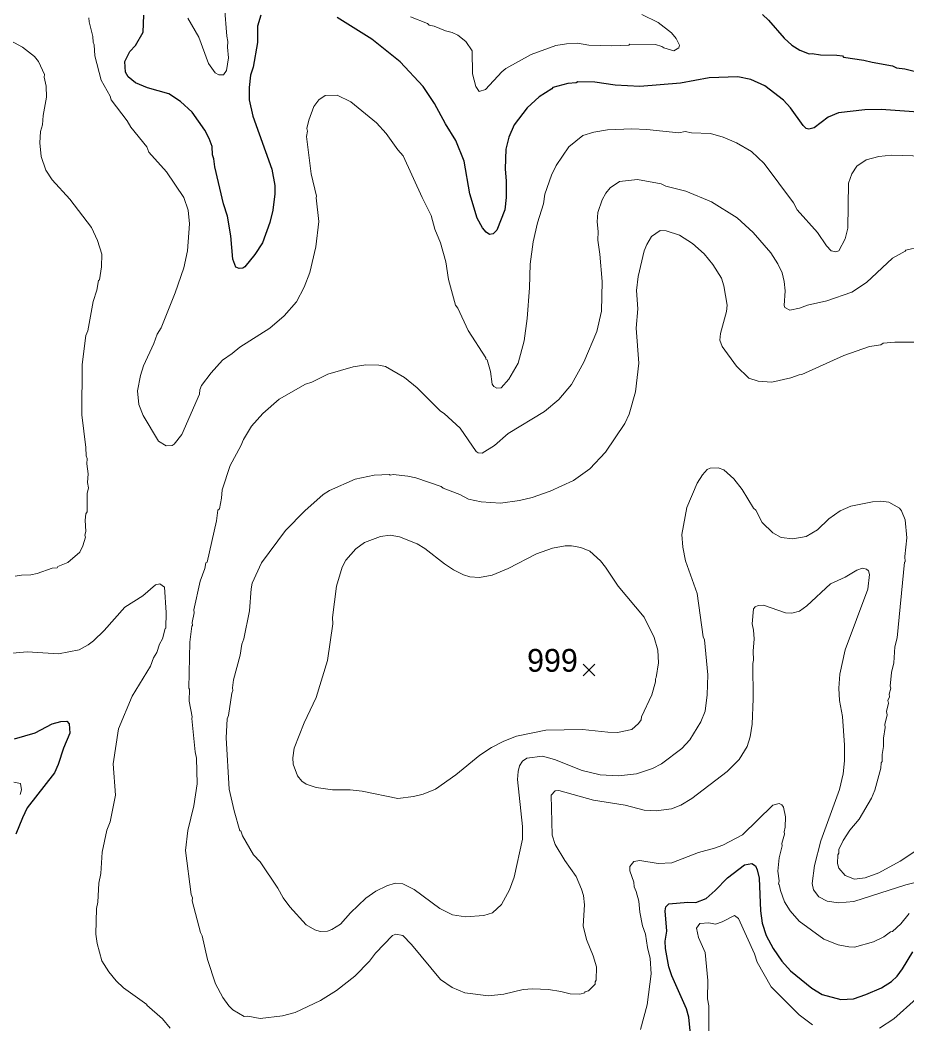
# Model space of a CAD drawing. Extents: x 265.7 to 292.1, y 7676.2 to 7704.2.
# Drawn here: x 279.917 to 283.035, y 7688.918 to 7692.446 of the extents above; entities that cross this region are included whole.
import ezdxf
from ezdxf.enums import TextEntityAlignment as Align

# ---------------------------------------------------------------- set-up
doc = ezdxf.new("R2010")
doc.units = 0
doc.header["$LTSCALE"] = 0.032
for name, color, linetype, lineweight in [('1', 7, 'Continuous', 25), ('2', 7, 'Continuous', 13), ('21', 7, 'Continuous', 25)]:
    doc.layers.add(name, color=color, linetype=linetype, lineweight=lineweight)
doc.layers.add('61', color=7, linetype='Continuous')

msp = doc.modelspace()

# ---------------------------------------------------------------- linework, layer by layer
at = {"layer": '1'}
for points in [[(280.8051, 7691.778), (280.7948, 7691.7349), (280.7692, 7691.6631), (280.7429, 7691.6224), (280.707, 7691.5793), (280.6998, 7691.5745), (280.6878, 7691.5729), (280.6751, 7691.5777), (280.6647, 7691.6057), (280.6575, 7691.6871), (280.6463, 7691.7573), (280.6328, 7691.8004), (280.6016, 7691.9296), (280.5985, 7691.9584), (280.5937, 7691.9727), (280.5921, 7692.0015), (280.5817, 7692.0302), (280.5665, 7692.0589), (280.5226, 7692.122), (280.4812, 7692.1594), (280.4397, 7692.1866), (280.3655, 7692.2081), (280.3224, 7692.2257), (280.2976, 7692.2464), (280.288, 7692.2624), (280.2857, 7692.2999), (280.3032, 7692.335), (280.3224, 7692.3565), (280.3495, 7692.4036), (280.3519, 7692.4627)], [(280.7636, 7692.4635), (280.7517, 7692.4244), (280.7517, 7692.3669), (280.7365, 7692.2807), (280.7277, 7692.252), (280.7221, 7692.2089)], [(283.1567, 7692.1164), (282.9445, 7692.1315), (282.887, 7692.1307), (282.7945, 7692.1203), (282.7577, 7692.1052), (282.7091, 7692.0677), (282.6899, 7692.0621), (282.6811, 7692.0645), (282.67, 7692.0749), (282.6253, 7692.1371), (282.6005, 7692.1642), (282.5351, 7692.2145), (282.4864, 7692.2368), (282.4402, 7692.2464), (282.3396, 7692.2424), (282.2391, 7692.2241), (282.0954, 7692.2121), (282.0093, 7692.2177), (281.9374, 7692.2273), (281.8784, 7692.2289), (281.872, 7692.2257), (281.8433, 7692.2233), (281.7898, 7692.2089), (281.7866, 7692.2041), (281.7419, 7692.1762), (281.7004, 7692.1371), (281.6542, 7692.0781), (281.6358, 7692.035), (281.6246, 7691.9919), (281.6222, 7691.9233), (281.6262, 7691.8802), (281.6262, 7691.8227), (281.6214, 7691.7796), (281.5927, 7691.7078), (281.5799, 7691.6942), (281.5672, 7691.6926), (281.556, 7691.7006), (281.5432, 7691.7158), (281.5241, 7691.7493), (281.4978, 7691.8355), (281.4778, 7691.9504), (281.4491, 7692.0222), (281.4124, 7692.0813), (281.3741, 7692.1531), (281.3342, 7692.2129), (281.2536, 7692.2991), (281.1538, 7692.3789), (281.0317, 7692.4555)], [(282.5271, 7692.4651), (282.5479, 7692.4459), (282.6029, 7692.3821), (282.6309, 7692.3573), (282.6588, 7692.3398), (282.6915, 7692.327), (282.7019, 7692.3286), (282.7306, 7692.3238), (282.7881, 7692.323), (282.808, 7692.3198), (282.812, 7692.3158), (282.8838, 7692.3055), (282.9126, 7692.2975), (282.9844, 7692.2847), (282.9987, 7692.2783), (283.0275, 7692.2751)], [(283.0275, 7692.2751), (283.0562, 7692.2672), (283.1424, 7692.26), (283.1942, 7692.2632), (283.1942, 7692.2656), (283.2142, 7692.272), (283.2405, 7692.2879)], [(280.7221, 7692.2089), (280.7229, 7692.1658), (280.7349, 7692.1084), (280.8027, 7691.9217), (280.8123, 7691.8642), (280.8123, 7691.8355), (280.8051, 7691.778)], [(279.8979, 7689.9196), (279.9697, 7689.9411), (280.0303, 7689.9722), (280.0606, 7689.981), (280.0814, 7689.9818), (280.0894, 7689.973), (280.0925, 7689.9403), (280.0702, 7689.8869), (280.051, 7689.8294), (280.0375, 7689.8007), (279.9425, 7689.677), (279.925, 7689.6427), (279.9026, 7689.5852)], [(282.2758, 7688.8703), (282.2678, 7688.9421), (282.2606, 7688.9708), (282.2079, 7689.0873), (282.1984, 7689.1192), (282.1856, 7689.1831), (282.1848, 7689.2094), (282.1904, 7689.2437), (282.1848, 7689.3155), (282.1872, 7689.3299), (282.1984, 7689.3402), (282.2646, 7689.3458), (282.2933, 7689.345), (282.3292, 7689.3594), (282.3604, 7689.3865), (282.4042, 7689.432), (282.4641, 7689.4767)], [(282.4641, 7689.4767), (282.4896, 7689.4823), (282.5024, 7689.4735), (282.5088, 7689.4592), (282.5152, 7689.4304), (282.5199, 7689.3155), (282.5263, 7689.2724)], [(282.5263, 7689.2724), (282.5399, 7689.2293), (282.5646, 7689.1831), (282.5957, 7689.1392), (282.6261, 7689.1049), (282.7011, 7689.0434), (282.737, 7689.0219), (282.8024, 7689.0043), (282.8471, 7689.0067), (282.8902, 7689.0211), (282.9453, 7689.045), (282.9812, 7689.0673), (283.0003, 7689.0857), (283.0195, 7689.1112), (283.0562, 7689.1719)]]:
    msp.add_lwpolyline(points, dxfattribs=at)
at = {"layer": '2'}
for points in [[(280.636, 7692.493), (280.6439, 7692.3893), (280.6479, 7692.3701), (280.6463, 7692.351), (280.6495, 7692.3127), (280.6423, 7692.2688), (280.6328, 7692.2536), (280.616, 7692.2536), (280.6025, 7692.2608), (280.5793, 7692.2935), (280.5458, 7692.3861), (280.5067, 7692.4531)], [(280.1596, 7692.4403), (280.1588, 7692.4539)], [(280.2338, 7692.1786), (280.2019, 7692.2345), (280.1803, 7692.3206), (280.1779, 7692.3589), (280.1739, 7692.3685), (280.1731, 7692.3877), (280.1596, 7692.4403)], [(282.1034, 7692.4659), (282.1609, 7692.4379), (282.2071, 7692.4012), (282.2231, 7692.3813), (282.2359, 7692.3581), (282.2335, 7692.3478), (282.2159, 7692.3382), (282.18, 7692.3478), (282.1728, 7692.3534), (282.1513, 7692.3597), (282.0603, 7692.3613), (282.0571, 7692.3581), (281.9965, 7692.3557), (281.9167, 7692.3581), (281.8768, 7692.3645), (281.8385, 7692.3629), (281.8002, 7692.3565), (281.714, 7692.3246), (281.6246, 7692.2752), (281.6103, 7692.264), (281.5536, 7692.2025), (281.5305, 7692.1954), (281.5193, 7692.2129), (281.5073, 7692.2568), (281.5065, 7692.3374), (281.4842, 7692.3701), (281.4563, 7692.3925), (281.4363, 7692.402), (281.4124, 7692.4076), (281.3725, 7692.4244), (281.3557, 7692.4284), (281.3493, 7692.434), (281.2895, 7692.4571)], [(279.8843, 7692.3725), (279.925, 7692.351), (279.9681, 7692.3174), (279.9816, 7692.3007), (280.0024, 7692.2544), (280.0016, 7692.2456), (280.0088, 7692.2137), (280.0096, 7692.1754), (279.9984, 7692.11), (279.996, 7692.0781), (279.9888, 7692.0541), (279.9864, 7692.0142), (279.9912, 7691.9664), (280.008, 7691.9185), (280.0303, 7691.885), (280.0918, 7691.8171), (280.1684, 7691.7174), (280.1891, 7691.6711), (280.2043, 7691.6232), (280.2035, 7691.5785), (280.1963, 7691.5331), (280.1923, 7691.5307), (280.1867, 7691.4972), (280.1739, 7691.4573), (280.1556, 7691.3535), (280.1484, 7691.3376), (280.1348, 7691.2354), (280.134, 7691.0583), (280.1484, 7690.9434), (280.1492, 7690.9146), (280.1524, 7690.9051), (280.1516, 7690.8859), (280.1564, 7690.8508), (280.1542, 7690.8205)], [(282.3444, 7692.0469), (282.2774, 7692.0493), (282.255, 7692.0541), (282.2327, 7692.0493), (282.121, 7692.0613), (282.0683, 7692.0637), (281.9821, 7692.0605), (281.9343, 7692.0525), (281.896, 7692.0398), (281.8465, 7691.9999), (281.8018, 7691.9344), (281.7858, 7691.9009), (281.7619, 7691.8339), (281.7571, 7691.8004), (281.7364, 7691.7333), (281.7204, 7691.6663), (281.71, 7691.5881), (281.7084, 7691.5051), (281.7004, 7691.3966), (281.6893, 7691.3184), (281.6685, 7691.2402), (281.6358, 7691.1843), (281.6079, 7691.1532), (281.5927, 7691.1524), (281.5823, 7691.158), (281.5768, 7691.166), (281.5712, 7691.2115), (281.5592, 7691.2522), (281.5544, 7691.2538), (281.5544, 7691.2586), (281.4922, 7691.3551), (281.4555, 7691.4333), (281.4475, 7691.4445), (281.4235, 7691.5339), (281.414, 7691.5961), (281.3956, 7691.6631), (281.3757, 7691.711), (281.3629, 7691.7589), (281.3302, 7691.8227), (281.264, 7691.9687), (281.2448, 7691.9895), (281.2041, 7692.0477), (281.1698, 7692.0845), (281.0804, 7692.1587), (281.0318, 7692.1818), (280.9895, 7692.181), (280.9679, 7692.1658), (280.9496, 7692.1419), (280.932, 7692.094), (280.9256, 7692.0653), (280.9272, 7692.0557), (280.924, 7692.0366), (280.9408, 7691.9057), (280.9591, 7691.8275), (280.9575, 7691.8211), (280.9671, 7691.7381), (280.9567, 7691.6488), (280.936, 7691.5594), (280.916, 7691.5067), (280.8889, 7691.4557), (280.845, 7691.4062), (280.7948, 7691.3631), (280.6894, 7691.2961), (280.6631, 7691.2745), (280.6288, 7691.2506), (280.5889, 7691.2059), (280.5554, 7691.162), (280.549, 7691.146), (280.5474, 7691.1309), (280.4859, 7690.9896), (280.4588, 7690.9553), (280.4516, 7690.9513), (280.4301, 7690.9497), (280.4038, 7690.9657), (280.3495, 7691.0567), (280.3351, 7691.095), (280.3303, 7691.1429), (280.3399, 7691.1971), (280.3511, 7691.2306), (280.387, 7691.3088), (280.399, 7691.3423), (280.4133, 7691.3647), (280.4628, 7691.4876), (280.4923, 7691.5754), (280.5059, 7691.6344), (280.5131, 7691.7302), (280.5075, 7691.778), (280.4931, 7691.8227), (280.4317, 7691.9121), (280.3702, 7691.9815), (280.3631, 7691.9999), (280.3064, 7692.0701), (280.2936, 7692.0924), (280.237, 7692.1658), (280.2338, 7692.1786)], [(282.6492, 7691.7788), (282.6365, 7691.8036), (282.5335, 7691.9416), (282.4888, 7691.9839), (282.4362, 7692.015), (282.3891, 7692.035), (282.3444, 7692.0469)], [(283.0929, 7691.9671), (282.9812, 7691.9711), (282.9365, 7691.9663), (282.8918, 7691.9544), (282.8591, 7691.932), (282.8415, 7691.9057), (282.8296, 7691.8722), (282.8272, 7691.7142), (282.8184, 7691.6767), (282.796, 7691.6352), (282.7849, 7691.6312), (282.7689, 7691.6344), (282.7522, 7691.652), (282.721, 7691.6998), (282.6492, 7691.7788)], [(283.0817, 7691.6488), (283.0314, 7691.6376), (283.0283, 7691.6336), (282.9844, 7691.6097), (282.8934, 7691.5235), (282.8415, 7691.4892), (282.753, 7691.4596), (282.6859, 7691.4437), (282.6572, 7691.4333), (282.6229, 7691.4269), (282.6061, 7691.4357), (282.6029, 7691.4429), (282.6069, 7691.494), (282.6037, 7691.5275), (282.5958, 7691.5578), (282.5814, 7691.5897), (282.5567, 7691.628), (282.4944, 7691.699), (282.4378, 7691.7509), (282.3476, 7691.8068), (282.2582, 7691.8451), (282.1872, 7691.8626), (282.1704, 7691.8706), (282.0875, 7691.8858), (282.0244, 7691.8786), (281.9917, 7691.8562), (281.9765, 7691.8379), (281.963, 7691.8147), (281.9478, 7691.7701), (281.9454, 7691.7365), (281.9494, 7691.703), (281.9486, 7691.6727), (281.9558, 7691.6232), (281.9638, 7691.5275), (281.9614, 7691.4229)], [(283.1041, 7691.3136), (282.9923, 7691.3136), (282.9516, 7691.3104), (282.9429, 7691.3048), (282.903, 7691.2992), (282.8136, 7691.2673), (282.6652, 7691.2003), (282.6556, 7691.1995), (282.6269, 7691.1883), (282.5599, 7691.1732), (282.512, 7691.1772), (282.4793, 7691.1875), (282.4362, 7691.2298), (282.3851, 7691.2993), (282.3771, 7691.3216), (282.3795, 7691.3439), (282.4003, 7691.4221), (282.4027, 7691.4445), (282.3907, 7691.5115), (282.3827, 7691.5394), (282.3524, 7691.5865), (282.3221, 7691.6248), (282.2806, 7691.6607), (282.2351, 7691.6895), (282.188, 7691.7054), (282.168, 7691.7062), (282.1369, 7691.6855), (282.1202, 7691.6567), (282.1114, 7691.6344), (282.0906, 7691.545), (282.0843, 7691.4956), (282.089, 7691.4317), (282.0827, 7691.3631), (282.093, 7691.2402), (282.0803, 7691.1397), (282.0587, 7691.0615), (282.0436, 7691.0279), (281.9749, 7690.9274), (281.9199, 7690.8684), (281.8624, 7690.8277), (281.7802, 7690.7901), (281.7172, 7690.7678), (281.6725, 7690.7574), (281.6055, 7690.7487), (281.5385, 7690.7526), (281.4938, 7690.7622), (281.4627, 7690.7782), (281.4044, 7690.8013), (281.3972, 7690.8069), (281.3087, 7690.8372), (281.2799, 7690.8436), (281.2289, 7690.8484), (281.2177, 7690.8468), (281.2161, 7690.8492), (281.1618, 7690.8468), (281.0948, 7690.8324), (281.0054, 7690.7933), (280.9831, 7690.779), (280.9176, 7690.7207), (280.8498, 7690.6521), (280.766, 7690.5388), (280.7333, 7690.467), (280.7293, 7690.447), (280.7237, 7690.3704), (280.7038, 7690.2715), (280.6966, 7690.2523), (280.691, 7690.214), (280.6679, 7690.1278), (280.6639, 7690.0991), (280.6655, 7690.0895), (280.6615, 7690.08), (280.6495, 7690.0018), (280.6447, 7689.9906), (280.6416, 7689.9236), (280.6527, 7689.7432), (280.6695, 7689.6666), (280.6894, 7689.5972), (280.6926, 7689.5972), (280.699, 7689.5789)], [(281.9614, 7691.4229), (281.9446, 7691.3519), (281.8991, 7691.2434), (281.856, 7691.1652), (281.8106, 7691.1125), (281.7603, 7691.0702), (281.6334, 7690.9928)], [(281.6334, 7690.9928), (281.5855, 7690.9505), (281.5417, 7690.9242), (281.5273, 7690.925), (281.5209, 7690.9298), (281.4642, 7691.012), (281.4084, 7691.0631), (281.3956, 7691.071), (281.3126, 7691.154), (281.2687, 7691.1899), (281.2017, 7691.2282), (281.1778, 7691.233), (281.1331, 7691.2338), (281.0884, 7691.2274), (280.999, 7691.2019), (280.9432, 7691.1732), (280.9208, 7691.1668), (280.8283, 7691.1133), (280.7708, 7691.0631), (280.7309, 7691.0184), (280.7022, 7690.9721), (280.6934, 7690.9497), (280.6559, 7690.8811), (280.628, 7690.7949), (280.6256, 7690.7662), (280.6176, 7690.7279), (280.6128, 7690.7231), (280.6072, 7690.6864), (280.5745, 7690.5412), (280.5697, 7690.538), (280.5665, 7690.5188), (280.5498, 7690.4742), (280.5282, 7690.3736), (280.529, 7690.3624), (280.5219, 7690.3289), (280.5227, 7690.3178), (280.5203, 7690.3154), (280.5139, 7690.2603), (280.5099, 7690.0983), (280.5131, 7690.0943), (280.5115, 7690.0528), (280.5219, 7689.997), (280.5203, 7689.9914), (280.5322, 7689.8741), (280.537, 7689.8518), (280.5394, 7689.7624), (280.5274, 7689.6842), (280.5067, 7689.598), (280.4987, 7689.5278), (280.5187, 7689.373), (280.5227, 7689.3618), (280.5219, 7689.3506), (280.5514, 7689.2389), (280.557, 7689.2277), (280.5761, 7689.1448), (280.604, 7689.0586), (280.6304, 7689.0107), (280.6511, 7688.9812), (280.6647, 7688.9676), (280.7054, 7688.9445), (280.7173, 7688.9453), (280.7612, 7688.9373), (280.8394, 7688.9461), (280.8841, 7688.9588), (280.9735, 7689.0003), (281.0294, 7689.0354), (281.094, 7689.0857), (281.1459, 7689.1384), (281.1666, 7689.1671), (281.2265, 7689.2285), (281.2384, 7689.2341), (281.2624, 7689.2293), (281.2927, 7689.1974), (281.3948, 7689.0745), (281.4363, 7689.0458), (281.481, 7689.0275), (281.564, 7689.0171), (281.6183, 7689.0227), (281.6853, 7689.0386), (281.7188, 7689.0418), (281.7747, 7689.0386), (281.8178, 7689.0322), (281.8513, 7689.0235), (281.8848, 7689.0227), (281.9023, 7689.0275), (281.9031, 7689.0306), (281.9159, 7689.0346), (281.939, 7689.0578), (281.939, 7689.0658), (281.943, 7689.0721), (281.9438, 7689.1192), (281.9319, 7689.1575), (281.9079, 7689.215), (281.8967, 7689.2629), (281.9015, 7689.3363)], [(280.9224, 7689.266), (280.9528, 7689.2485), (280.9719, 7689.2429), (280.9974, 7689.2437), (281.0134, 7689.2501), (281.0437, 7689.2692), (281.0788, 7689.3083), (281.1331, 7689.3602), (281.1682, 7689.3849), (281.2065, 7689.4033), (281.2352, 7689.4129), (281.2624, 7689.4105), (281.3023, 7689.3905), (281.3932, 7689.3235), (281.4379, 7689.3012), (281.4826, 7689.2948), (281.548, 7689.2996), (281.5776, 7689.3083), (281.6095, 7689.3379), (281.6374, 7689.3889), (281.6542, 7689.4336), (281.6829, 7689.5677), (281.6837, 7689.6124), (281.6661, 7689.7767), (281.6677, 7689.8055), (281.6725, 7689.8246), (281.6829, 7689.8414), (281.6981, 7689.8517), (281.7539, 7689.8589), (281.7954, 7689.8478), (281.8928, 7689.8087), (281.9566, 7689.7935), (282.0204, 7689.7895), (282.0843, 7689.7975), (282.1401, 7689.8158), (282.172, 7689.8318), (282.2439, 7689.8861), (282.2718, 7689.9164), (282.3109, 7689.9794), (282.3252, 7690.0177), (282.3332, 7690.0752), (282.3348, 7690.1454), (282.3229, 7690.2683), (282.3189, 7690.2779), (282.2981, 7690.4311), (282.2566, 7690.546), (282.247, 7690.5939), (282.2439, 7690.6385), (282.2614, 7690.7327), (282.2981, 7690.8189), (282.3157, 7690.8476), (282.3332, 7690.866), (282.3428, 7690.8707), (282.3715, 7690.8723), (282.3907, 7690.8652), (282.4266, 7690.8332), (282.4553, 7690.7965), (282.4952, 7690.7311), (282.5032, 7690.7231), (282.5255, 7690.6808), (282.563, 7690.6441), (282.5934, 7690.6274), (282.6333, 7690.6226), (282.6811, 7690.6306), (282.721, 7690.6545), (282.7601, 7690.6936), (282.8008, 7690.7215), (282.8375, 7690.7375), (282.9141, 7690.7526), (282.9429, 7690.755), (282.9716, 7690.7519), (283.0083, 7690.7311), (283.0163, 7690.7215), (283.029, 7690.6896), (283.0346, 7690.6258), (283.0275, 7690.5603), (283.0283, 7690.542), (283.0259, 7690.5404), (283.0003, 7690.2747), (282.9923, 7690.2428), (282.9891, 7690.1869), (282.9812, 7690.1534), (282.9764, 7690.1055), (282.978, 7690.0975), (282.9724, 7690.0768), (282.974, 7690.068), (282.9684, 7690.0544), (282.97, 7690.0449), (282.9636, 7690.0161), (282.9652, 7690.0042), (282.9572, 7689.9699), (282.9588, 7689.9603), (282.9532, 7689.922), (282.9532, 7689.8932), (282.9477, 7689.8645)], [(280.1542, 7690.8205), (280.158, 7690.8021), (280.1532, 7690.7822), (280.1532, 7690.7175), (280.1484, 7690.7104), (280.146, 7690.688), (280.1484, 7690.6489), (280.1452, 7690.6353), (280.1468, 7690.6282), (280.138, 7690.5986), (280.1269, 7690.5763), (280.0854, 7690.5396), (280.0503, 7690.5252), (280.0479, 7690.5212), (280.0303, 7690.5196), (279.9777, 7690.5013), (279.9553, 7690.4965), (279.9218, 7690.4957), (279.8995, 7690.4917)], [(281.7874, 7689.582), (281.7842, 7689.7225), (281.7986, 7689.7368), (281.8114, 7689.7384), (281.9327, 7689.7049), (282.0444, 7689.6866), (282.1114, 7689.669), (282.1529, 7689.6666), (282.2072, 7689.6738), (282.2399, 7689.6874), (282.279, 7689.7105), (282.4035, 7689.8055), (282.4449, 7689.8478), (282.4737, 7689.8932), (282.484, 7689.9268), (282.4912, 7689.9714), (282.4944, 7690.0608), (282.4928, 7690.1853), (282.496, 7690.1965), (282.4944, 7690.2284), (282.4976, 7690.2715), (282.496, 7690.3018), (282.4912, 7690.3241), (282.4952, 7690.3768), (282.5016, 7690.384), (282.512, 7690.3888), (282.5311, 7690.3896), (282.6077, 7690.3632), (282.6301, 7690.3616), (282.6572, 7690.3688), (282.6827, 7690.3872), (282.7657, 7690.4646), (282.8184, 7690.4885), (282.8583, 7690.5125), (282.879, 7690.5196), (282.8934, 7690.5164), (282.8998, 7690.5101), (282.9038, 7690.4981), (282.8974, 7690.4462), (282.8176, 7690.2332), (282.7992, 7690.147), (282.796, 7690.0975), (282.7984, 7690.0544), (282.808, 7689.9986), (282.816, 7689.898), (282.8152, 7689.8422), (282.8104, 7689.7975), (282.7976, 7689.7416), (282.7322, 7689.5613), (282.7099, 7689.4751), (282.7019, 7689.4113), (282.7067, 7689.3897), (282.7258, 7689.365), (282.7546, 7689.349), (282.7945, 7689.3442), (282.8479, 7689.3482), (283.0307, 7689.4073), (283.1551, 7689.4376)], [(279.826, 7690.2156), (279.9425, 7690.2252), (280.0527, 7690.2188), (280.1253, 7690.2332), (280.1564, 7690.2499), (280.1755, 7690.2643), (280.2122, 7690.3002), (280.2849, 7690.3832), (280.3487, 7690.4231), (280.3934, 7690.4614), (280.4078, 7690.4646), (280.4245, 7690.4526), (280.4309, 7690.364), (280.4293, 7690.309), (280.4269, 7690.3082), (280.4181, 7690.2715), (280.4069, 7690.2523)], [(280.4069, 7690.2523), (280.3974, 7690.2236), (280.3862, 7690.2045), (280.375, 7690.1757), (280.3112, 7690.0696), (280.2633, 7689.9555), (280.2442, 7689.8326)], [(282.9477, 7689.8645), (282.9477, 7689.8398), (282.9445, 7689.8358), (282.9429, 7689.8166), (282.9221, 7689.74), (282.9109, 7689.7113), (282.8671, 7689.6379)], [(280.2442, 7689.8326), (280.2521, 7689.7225), (280.2338, 7689.6283), (280.2218, 7689.5996), (280.2059, 7689.5222), (280.2011, 7689.4464), (280.1939, 7689.4129), (280.1907, 7689.3458), (280.1859, 7689.3235), (280.1835, 7689.2341), (280.1883, 7689.2006), (280.2043, 7689.14), (280.229, 7689.1017), (280.2553, 7689.0698), (280.2809, 7689.045), (280.3623, 7688.9868), (280.3623, 7688.9836), (280.4173, 7688.9357), (280.4445, 7688.903)], [(279.8947, 7689.7672), (279.9186, 7689.7632), (279.9218, 7689.7408), (279.917, 7689.7249)], [(282.0978, 7688.899), (282.1218, 7688.9852), (282.1353, 7689.0937), (282.1321, 7689.148), (282.1226, 7689.1863), (282.1162, 7689.2341), (282.1058, 7689.2629), (282.0954, 7689.3107), (282.0922, 7689.349), (282.0835, 7689.3841), (282.0763, 7689.4001), (282.0747, 7689.4161), (282.0611, 7689.456), (282.0611, 7689.4719), (282.0747, 7689.4895), (282.0954, 7689.4927), (282.1609, 7689.4823), (282.2088, 7689.4839), (282.3021, 7689.5206), (282.3588, 7689.5358), (282.3875, 7689.5469), (282.4569, 7689.5828), (282.5638, 7689.6874), (282.5862, 7689.6922), (282.595, 7689.6882), (282.6013, 7689.6802), (282.6085, 7689.6459), (282.6069, 7689.6092), (282.6029, 7689.5932), (282.6045, 7689.5852), (282.595, 7689.5517), (282.5966, 7689.5437), (282.5854, 7689.5022), (282.5814, 7689.4544), (282.5854, 7689.4209), (282.5838, 7689.4089), (282.5862, 7689.4081), (282.5902, 7689.3873), (282.6045, 7689.3474), (282.6245, 7689.3155), (282.6564, 7689.2788), (282.7426, 7689.2158), (282.7929, 7689.1966), (282.8312, 7689.1886), (282.8503, 7689.1878), (282.9173, 7689.2062), (282.954, 7689.2238), (282.9772, 7689.2413), (282.9844, 7689.2429), (283.0131, 7689.27), (283.0434, 7689.3067)], [(282.8671, 7689.6379), (282.8343, 7689.5988), (282.8104, 7689.5629), (282.796, 7689.531), (282.796, 7689.5182), (282.7921, 7689.5118), (282.7913, 7689.4815), (282.796, 7689.4655), (282.8176, 7689.4392), (282.8503, 7689.4264), (282.8886, 7689.432), (282.9365, 7689.4496), (283.0115, 7689.4903), (283.0945, 7689.5453)], [(280.699, 7689.5789), (280.7381, 7689.5118), (280.7612, 7689.4879), (280.8235, 7689.3953), (280.8418, 7689.3618), (280.865, 7689.3299), (280.9224, 7689.266)], [(281.9015, 7689.3363), (281.8975, 7689.3698), (281.8912, 7689.3921), (281.872, 7689.4368), (281.8321, 7689.4927), (281.7978, 7689.5485), (281.7874, 7689.582)], [(282.338, 7688.8607), (282.338, 7688.982), (282.334, 7689.0059), (282.3356, 7689.0713), (282.3252, 7689.1687), (282.3021, 7689.2214), (282.2949, 7689.2549), (282.3069, 7689.2716), (282.338, 7689.2732), (282.362, 7689.2692), (282.3859, 7689.2772), (282.4282, 7689.2996), (282.4426, 7689.2884), (282.4992, 7689.1647), (282.5088, 7689.1352), (282.5575, 7689.049), (282.6556, 7688.95), (282.7035, 7688.9149)], [(282.9381, 7688.9038), (282.9892, 7688.9357), (283.0674, 7689.0067)]]:
    msp.add_lwpolyline(points, dxfattribs=at)
msp.add_lwpolyline([(281.2457, 7689.7103), (281.3007, 7689.7169), (281.3342, 7689.7257), (281.3773, 7689.7432), (281.4491, 7689.7935), (281.5337, 7689.8621), (281.5744, 7689.8892), (281.6183, 7689.9124), (281.6629, 7689.9291), (281.7651, 7689.9499), (281.8944, 7689.9531), (281.9837, 7689.9435), (282.0172, 7689.9427), (282.0683, 7689.9523), (282.0914, 7689.9738), (282.1002, 7689.9866), (282.1018, 7689.997), (282.1377, 7690.0752), (282.1513, 7690.1199), (282.1505, 7690.131), (282.1537, 7690.1358), (282.1617, 7690.1869), (282.1593, 7690.2316), (282.1465, 7690.2763), (282.1114, 7690.3481), (282.0196, 7690.4566), (281.9757, 7690.5236), (281.9574, 7690.546), (281.9207, 7690.5795), (281.888, 7690.5923), (281.8561, 7690.5986), (281.8337, 7690.5978), (281.789, 7690.5899), (281.7332, 7690.5699), (281.6326, 7690.5188), (281.5768, 7690.4949), (281.5321, 7690.4869), (281.4986, 7690.4893), (281.4762, 7690.4965), (281.4411, 7690.5141), (281.4092, 7690.5348), (281.3406, 7690.5891), (281.3126, 7690.605), (281.2512, 7690.6298), (281.2177, 7690.6353), (281.1842, 7690.6306), (281.1283, 7690.6098), (281.0972, 7690.5875), (281.0621, 7690.5484), (281.0493, 7690.5236), (281.0294, 7690.4566), (281.015, 7690.3465), (281.0166, 7690.3241), (280.9974, 7690.1949), (280.9575, 7690.0656), (280.916, 7689.9762), (280.8809, 7689.8869), (280.8754, 7689.8533), (280.8777, 7689.831), (280.8921, 7689.7895), (280.9081, 7689.7712), (280.9232, 7689.7608), (280.9575, 7689.7488), (281.015, 7689.7408), (281.0772, 7689.7408), (281.1203, 7689.736)], close=True, dxfattribs=at)
at = {"layer": '21'}
for p, q in [((281.897, 7690.1822), (281.9382, 7690.141)), ((281.9382, 7690.1822), (281.897, 7690.141))]:
    msp.add_line(p, q, dxfattribs=at)

# ---------------------------------------------------------------- texts
at = {"layer": '61'}
msp.add_text('999', height=0.08, dxfattribs=at).set_placement((281.7887, 7690.1558), align=Align.CENTER)

doc.saveas('drawing.dxf')
